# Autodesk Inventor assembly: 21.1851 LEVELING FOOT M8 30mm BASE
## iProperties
Created: 2007-03
Part Number: 21.1851 LEVELING FOOT M8 30mm BASE
Document SubType Name: Assembly
Designer: Andy Moles
Mass: 55.3971 g
Surface Area: 76.5754 cm^2
Volume: 14.9626 cm^3
Density: 3.70237 g/cm^3
Author: Andy Moles
